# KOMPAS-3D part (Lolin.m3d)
File: created 12.09.2016 00:20:07, last saved 14.09.2016 00:43:00.
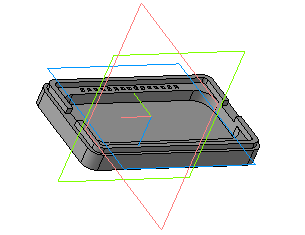
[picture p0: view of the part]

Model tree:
1. Эскиз:1
2. Операция выдавливания:1
     Расстояние 1 = 6
3. Эскиз:2
4. Операция выдавливания:2
     Расстояние 1 = 20; Расстояние 2 = 2
5. Эскиз:3
6. Эскиз:4
7. Эскиз:5
8. Вырезать элемент выдавливания:2
     Расстояние 1 = 4
9. Эскиз:6
10. Вырезать элемент выдавливания:3
     Расстояние 1 = 4
11. Эскиз:7
12. Вырезать элемент выдавливания:4
     Расстояние 1 = 4
13. Эскиз:19
14. Вырезать элемент выдавливания:7
     Расстояние 1 = 6
15. Массив по сетке:6  (with: Вырезать элемент выдавливания:7)  (2 pattern instances)
     Наклон = 90; Шаг 1 = 28; Угол раствора = 90; Номер 1 = 1
16. Массив по сетке:7  (with: Вырезать элемент выдавливания:7)  (15 pattern instances)
     Наклон = 180; Шаг 1 = 2.54; Угол раствора = 90; Номер 1 = 1
17. Массив по сетке:8  (with: Массив по сетке:6, Вырезать элемент выдавливания:7)  (43 pattern instances)
     Наклон = 180; Шаг 1 = 2.54; Угол раствора = 90; Номер 1 = 1
18. Эскиз:20
19. Вырезать элемент выдавливания:8
     Расстояние 1 = 2
20. Эскиз:21
21. Операция выдавливания:3
     Расстояние 1 = 4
